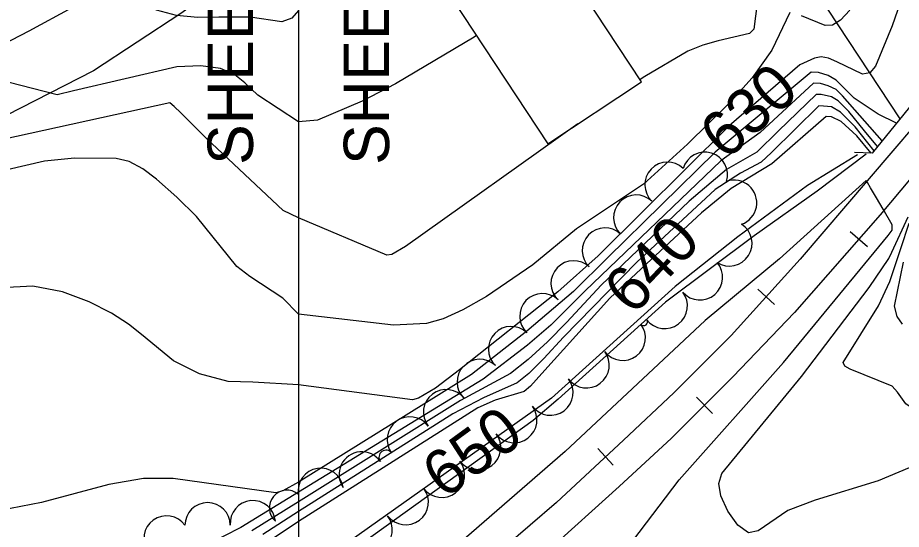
# Model space of a CAD drawing. Extents: x 79600 to 91800, y 75600 to 84400.
# Drawn here: x 84876.3 to 85265.8, y 82239.4 to 82464.8 of the extents above; entities that cross this region are included whole.
import ezdxf

# ---------------------------------------------------------------- set-up
doc = ezdxf.new("R2010")
doc.units = 0
for name, color, linetype in [('084-085$0$GRID', 7, 'Continuous'), ('084-085$0$INDEX', 7, 'Continuous'), ('084-085$0$INTER', 7, 'Continuous'), ('084-085$0$ROAD', 7, 'Continuous'), ('084-085$0$TI_SHEET', 7, 'Continuous'), ('084-085$0$TREES', 7, 'Continuous'), ('084-090$0$BLDG', 7, 'Continuous'), ('084-090$0$BRIDGE', 7, 'Continuous'), ('084-090$0$GRID', 7, 'Continuous'), ('084-090$0$INDEX', 7, 'Continuous'), ('084-090$0$INDXLBL', 7, 'Continuous'), ('084-090$0$INTER', 7, 'Continuous'), ('084-090$0$ROAD', 7, 'Continuous'), ('084-090$0$RR', 7, 'Continuous'), ('084-090$0$TI_SHEET', 7, 'Continuous'), ('084-090$0$TREES', 7, 'Continuous')]:
    doc.layers.add(name, color=color, linetype=linetype)

# ---------------------------------------------------------------- blocks, each defined once
blk = doc.blocks.new('084-090$0$RRTICK100')
blk.add_line((0, -5), (0, 5))

msp = doc.modelspace()

# ---------------------------------------------------------------- linework, layer by layer
at = {"layer": '084-085$0$GRID'}
msp.add_line((85000, 84000), (85000, 80000), dxfattribs=at)
at = {"layer": '084-085$0$INDEX'}
for points in [[(85000, 82303.04), (84979.93, 82304.26), (84969.03, 82304.58), (84956.4, 82307.95), (84944.99, 82313.68), (84930.81, 82325.16), (84925.08, 82329.73), (84917.59, 82334.63), (84907.75, 82339.66), (84895.97, 82343.97), (84882.92, 82346.55), (84843.28, 82344.4), (84808.97, 82345.03), (84798.34, 82343.88), (84787.45, 82341.31)], [(85000, 82242.85), (84981.79, 82230.57)]]:
    msp.add_lwpolyline(points, dxfattribs=at)
at = {"layer": '084-085$0$INTER'}
for points in [[(85000, 82468.03), (84997.16, 82464.63), (84992.74, 82463.02), (84978.7, 82465.06), (84964.89, 82465.11), (84955.7, 82464.96), (84946.24, 82465.81), (84937.48, 82468.22), (84930.08, 82471.41), (84924.64, 82474.25), (84921.56, 82475.99), (84920.44, 82477.28), (84923.96, 82489.01), (84924.41, 82490.84), (84917.34, 82499.54), (84906.76, 82518.7), (84892.54, 82541.22), (84878.81, 82560.85), (84872.17, 82570.21)], [(85000, 82418.99), (84982.18, 82430.67), (84976.43, 82436.1), (84971.99, 82439.7), (84965.66, 82442.51), (84957.03, 82443.63), (84946.44, 82443.11), (84900.89, 82432.62), (84893.67, 82430.83), (84866.72, 82437.76)], [(85000, 82376.71), (84993.36, 82379.83), (84959.35, 82411.78), (84948.22, 82422.85), (84945.33, 82425.71), (84943.35, 82427.35), (84863.6, 82409.82), (84852.82, 82407.06), (84839.68, 82405.95), (84819.07, 82408.01), (84811.74, 82408.37), (84803.14, 82407.64), (84782.74, 82402.54), (84765.75, 82396.19), (84761.62, 82394.72), (84760.1, 82394.54), (84758.88, 82394.6), (84783.68, 82416.29), (84789.97, 82421.91), (84801.36, 82436.99)], [(85000, 82334.2), (84993.22, 82341.21), (84978.62, 82350.73), (84972.86, 82355.26), (84955.1, 82377.29), (84946.41, 82385.79), (84937.52, 82393.7), (84931.52, 82398.2), (84925.37, 82401.5), (84919.66, 82402.75), (84901.37, 82402.91), (84888.09, 82401.62), (84871.65, 82397.76)], [(85000, 82260.1), (84993.19, 82256.36), (84990.13, 82255.53), (84944.8, 82261.74), (84931.69, 82261.79), (84916.48, 82259.17), (84886.85, 82251.18), (84868.55, 82247.65), (84865.13, 82247.06)], [(85000, 82255.78), (84974.68, 82240.16), (84922.2, 82213.43)], [(85000, 82251.47), (84979.49, 82238.65)], [(85000, 82247.16), (84984.3, 82237.15)]]:
    msp.add_lwpolyline(points, dxfattribs=at)
at = {"layer": '084-085$0$ROAD'}
for points in [[(84429.82, 82231.01), (84518.24, 82275.92), (84634.39, 82333.42), (84774.34, 82403.66), (84881.4, 82459.07), (84900.29, 82469.29), (84916.55, 82479.79), (84937.27, 82492.66), (84969.9, 82518.15), (84999.9, 82544.53), (85000, 82544.64)], [(85000, 82507.03), (84975.62, 82486.4), (84948.18, 82466.67), (84909.67, 82441.44), (84871.27, 82421.76), (84821.34, 82396.87), (84727.19, 82347.77), (84586.14, 82278.6), (84439.32, 82205.29)]]:
    msp.add_lwpolyline(points, dxfattribs=at)
at = {"layer": '084-085$0$TREES'}
for centre, radius, start, end in [((84994.97, 82248.85), 7.78, 49.6715, 229.6715), ((84960.01, 82241.17), 10, 0.079, 180.079), ((84979.97, 82242.05), 10, 4.9829, 184.9829), ((84941.88, 82235.33), 10, 35.6147, 215.6147)]:
    msp.add_arc(centre, radius, start, end, dxfattribs=at)
at = {"layer": '084-090$0$BLDG'}
msp.add_lwpolyline([(85091.05, 82518.75), (85074.45, 82543.94), (85041.43, 82522.18), (85057.9, 82497.19), (85053.8, 82494.49), (85109.95, 82409.3), (85151.3, 82436.55), (85095.28, 82521.54)], close=True, dxfattribs=at)
at = {"layer": '084-090$0$BRIDGE'}
msp.add_lwpolyline([(85295.42, 82464.24), (85296.7, 82459), (85252.93, 82405.15), (85245.2, 82405.39)], dxfattribs=at)
at = {"layer": '084-090$0$GRID'}
msp.add_line((85000, 84000), (85000, 80000), dxfattribs=at)
at = {"layer": '084-090$0$INDEX'}
for points in [[(85266.41, 82474.95), (85261.78, 82461.24), (85254.41, 82443.41), (85251.89, 82440.49), (85248.68, 82440), (85237.28, 82445.41), (85233.7, 82446.93), (85230.43, 82447.55), (85227.56, 82447.07), (85221.06, 82444.01), (85189.83, 82417.17), (85132.21, 82359.87), (85114.36, 82344.02), (85071.03, 82309.73), (85060.47, 82301.58), (85052.89, 82297.2), (85050.26, 82296.38), (85000, 82303.04)], [(85252.45, 82405.17), (85246.1, 82412.84), (85239.3, 82419.08), (85235.02, 82421.2), (85232.57, 82421.33), (85208.76, 82400.45), (85190.83, 82389.61), (85177.68, 82378.9), (85153.47, 82356.43), (85137.26, 82341.3), (85107.25, 82308.02), (85102.29, 82302.45), (85099.59, 82300.15), (85086.68, 82296.3), (85079.13, 82292.89), (85000, 82242.85)], [(85246.39, 82404.37), (85224.48, 82390.93), (85193.73, 82368.28), (85166.04, 82346.44), (85111.65, 82297.15), (85000, 82218.08)], [(85338.61, 82255.23), (85337.37, 82256.23), (85333.4, 82258.83), (85328.67, 82259.47), (85308.04, 82269.65), (85278.7, 82287.12), (85267.73, 82294.7), (85264.1, 82299.83), (85261.74, 82302.49), (85243.28, 82309.97), (85240.85, 82311.31), (85240.2, 82312.91), (85255.64, 82337.87), (85260.64, 82348.6), (85264.84, 82360.95), (85265.5, 82363.18), (85269.16, 82374.24)]]:
    msp.add_lwpolyline(points, dxfattribs=at)
at = {"layer": '084-090$0$INTER'}
for points in [[(85278.8, 82583.44), (85260.9, 82565.03), (85247.1, 82553.56), (85242.78, 82550), (85240.21, 82546.93), (85234.45, 82523.49), (85232.69, 82516.57), (85223.98, 82498.18), (85220.75, 82492.17), (85218.66, 82488.96), (85212.17, 82489.31), (85208.71, 82488.99), (85205.58, 82486.14), (85203.43, 82479.96), (85201.43, 82465.47), (85200.78, 82459.73), (85198.83, 82457.92), (85185.02, 82454.57), (85178.34, 82452.67), (85171.61, 82450.07), (85152.67, 82438.96), (85150.65, 82437.53)], [(85216.67, 82467.06), (85208.75, 82450.49), (85200.09, 82438.29), (85190.41, 82427.77), (85171.51, 82409.06), (85152.18, 82391.54), (85122.64, 82371.72), (85103.4, 82355.86), (85082.97, 82341.98), (85072.52, 82336.06), (85063.86, 82332.18), (85056.49, 82330.13), (85041.9, 82329.41), (85000, 82334.2)], [(85243.08, 82468.14), (85239, 82463.69), (85235.45, 82461.56), (85232.22, 82461.39), (85221.78, 82465.7)], [(85078.56, 82456.92), (85077.51, 82456.25), (85042.84, 82435.7), (85028.18, 82428.07), (85008.47, 82419.66), (85000, 82418.99)], [(85263.66, 82418.36), (85255.56, 82422.34), (85244.95, 82429.35), (85237.07, 82437.23), (85233.55, 82439.29), (85229.24, 82440.62), (85226.05, 82440.78), (85183.68, 82405.56), (85136.46, 82359.18), (85121.26, 82344.19), (85100.77, 82326.7), (85076.25, 82307.62), (85000, 82260.1)], [(85257.33, 82410.57), (85239.85, 82430.38), (85236.98, 82433.24), (85233.54, 82434.75), (85230.18, 82435.84), (85227.06, 82435.94), (85203.53, 82414.3), (85186.2, 82401.74), (85126.48, 82344.42), (85111.29, 82329.33), (85101.05, 82320.49), (85081.48, 82305.51), (85000, 82255.78)], [(85255.27, 82408.04), (85249.5, 82414.99), (85242.64, 82423.53), (85237.95, 82428.22), (85235.06, 82429.93), (85230.39, 82430.94), (85228.22, 82430.92), (85211.61, 82415.01), (85202.03, 82405.64), (85188.72, 82397.93), (85172.21, 82383.98), (85133.49, 82346.99), (85118.31, 82330.73), (85109.76, 82321.99), (85101.34, 82314.28), (85093.51, 82308), (85071.46, 82296.21), (85000, 82251.47)], [(85253.8, 82406.23), (85245.43, 82416.69), (85238.92, 82423.21), (85235.04, 82425.51), (85231.47, 82425.88), (85229.46, 82425.98), (85208.53, 82405.47), (85203.99, 82401.13), (85194.88, 82396.25), (85183.66, 82389.15), (85149.21, 82357.11), (85116.84, 82324), (85108.22, 82314.64), (85101.63, 82308.06), (85096.51, 82303.9), (85081.57, 82297.38), (85068.05, 82290.28), (85000, 82247.16)], [(85123.14, 82417.99), (85047.22, 82364.07), (85041.27, 82360.47), (85038.98, 82360.17), (85000, 82376.71)], [(85250.24, 82404.69), (85228.72, 82388.39), (85200.87, 82368.76), (85161.87, 82339.55), (85114.58, 82296.72), (85103.55, 82287.37), (85000, 82212.97)], [(85147.49, 82234.27), (85167.84, 82261.22), (85213.85, 82312.95), (85247.63, 82353.9), (85259.95, 82368.81), (85261.71, 82371.22), (85261.69, 82373.58), (85257.79, 82380.46), (85254.8, 82385.52), (85252.25, 82389.82), (85250.82, 82392.22), (85250.29, 82393.11), (85212.01, 82358.58), (85179.38, 82331.38), (85117.6, 82273.68), (85051.74, 82216.46)], [(85323.86, 82256.54), (85323.1, 82257.26), (85315.47, 82261.78), (85298.34, 82268.5), (85292.66, 82271.62), (85288.4, 82272.73), (85282.88, 82272.27), (85255.53, 82260.76), (85227.74, 82252.24), (85215.82, 82247.67), (85202.65, 82238.73), (85198.4, 82237.85), (85193.73, 82241.27), (85189.29, 82247.43), (85186.22, 82254.1), (85185.4, 82259.54), (85186.65, 82264.05), (85221.71, 82306.79), (85251.63, 82345.88), (85260.29, 82358.71), (85261.55, 82361.46), (85268.84, 82377.12)], [(85266.3, 82329.85), (85263.95, 82333.09), (85262.69, 82337.74), (85266.75, 82357.11)]]:
    msp.add_lwpolyline(points, dxfattribs=at)
at = {"layer": '084-090$0$ROAD'}
msp.add_lwpolyline([(85265.2, 82420.25), (85137.7, 82613.67), (85129.47, 82618.38), (85119.56, 82620.9), (85112.63, 82619.75), (85105.26, 82615.2), (85061.86, 82569.85), (85026.42, 82532.29), (85000.73, 82507.64), (85000, 82507.03)], dxfattribs=at)
at = {"layer": '084-090$0$RR'}
for points in [[(86153.28, 83943.88), (85933.9, 83485.8), (85758.12, 83119.71), (85690.49, 82979.78), (85674.9, 82948.29), (85659.44, 82919.26), (85642.77, 82887.91), (85628.81, 82863.07), (85611.2, 82832.49), (85591.44, 82800.8), (85571.68, 82769.57), (85544.13, 82730.24), (85511.37, 82685.91), (85471.43, 82634.57), (85256.44, 82378.02), (85218.73, 82334.88), (85191.53, 82306.51), (85164.47, 82279.53), (85141.37, 82258.31), (85109.84, 82229.74), (85084.12, 82208.03), (85052.41, 82183.17), (85018.39, 82157.2), (85000, 82144.89)], [(86139.68, 83943.87), (86090.93, 83842.75), (85923.18, 83492.02), (85725.74, 83083.88), (85678.84, 82986.92), (85656.12, 82942.7), (85643.25, 82917.41), (85629, 82890.71), (85615.33, 82867.42), (85596.8, 82836.67), (85573.71, 82798.77), (85557.74, 82774.06), (85536.59, 82743.44), (85505.99, 82699.75), (85477.03, 82661.95), (85312.39, 82465.02), (85221.12, 82358.37), (85190.73, 82324.72), (85165.51, 82299.46), (85143.33, 82278.71), (85113.8, 82251.24), (85078.9, 82221.26)]]:
    msp.add_lwpolyline(points, dxfattribs=at)
at = {"layer": '084-090$0$TREES'}
for centre, radius, start, end in [((85179.2, 82395.57), 10, 343.3041, 163.3041), ((85162.73, 82391.2), 10, 46.399, 226.399), ((85192.07, 82383.25), 10, 289.1755, 109.1755), ((85148.94, 82376.72), 10, 46.399, 226.399), ((85189.97, 82365.38), 10, 237.4378, 57.4378), ((85135.14, 82362.24), 10, 46.399, 226.399), ((85121.35, 82347.75), 10, 46.399, 226.399), ((85177.02, 82350.42), 10, 220.7876, 40.7876), ((85107.56, 82333.27), 10, 46.399, 226.399), ((85161.49, 82337.82), 10, 217.348, 37.348), ((85152.26, 82330.78), 1.61, 217.1281, 37.1281), ((85093.77, 82318.79), 10, 46.399, 226.399), ((85143, 82323.77), 10, 217.1281, 37.1281), ((85127.05, 82311.7), 10, 217.1281, 37.1281), ((85079.97, 82304.3), 10, 46.399, 226.399), ((85111.11, 82299.63), 10, 217.1281, 37.1281), ((85065.14, 82290.98), 10, 37.441, 217.441), ((85095.16, 82287.55), 10, 217.1281, 37.1281), ((85049.16, 82278.95), 10, 36.5564, 216.5564), ((85079.22, 82275.48), 10, 217.1281, 37.1281), ((85027.96, 82263.55), 10, 35.0594, 215.0594), ((85038.64, 82271.14), 3.11, 36.5564, 216.5564), ((85063.27, 82263.41), 10, 217.1281, 37.1281), ((85009.88, 82256.29), 10, 8.699, 188.699), ((85047.32, 82251.34), 10, 217.1281, 37.1281), ((85031.38, 82239.27), 10, 217.1281, 37.1281)]:
    msp.add_arc(centre, radius, start, end, dxfattribs=at)

# ---------------------------------------------------------------- block references
at = {"layer": '084-090$0$RR'}
for p, rotation in [((85247.04, 82367.26), -131.15676236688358), ((85206.17, 82341.82), -132.088466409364), ((85179, 82294.02), -135.08800536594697), ((85135.35, 82271.29), -137.07119198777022)]:
    msp.add_blockref('084-090$0$RRTICK100', p, dxfattribs=dict(at, rotation=rotation))

# ---------------------------------------------------------------- texts
at = {"layer": '084-085$0$TI_SHEET'}
msp.add_text('SHEET', height=20, rotation=90, dxfattribs=at).set_placement((85040, 82400))
at = {"layer": '084-090$0$INDXLBL'}
for s, rotation, p in [('630', 42.0778, (85188.46, 82401.52)), ('640', 46.7243, (85147.57, 82333.15)), ('650', 36.1085, (85064.32, 82252.36))]:
    msp.add_text(s, height=20, rotation=rotation, dxfattribs=at).set_placement(p)
at = {"layer": '084-090$0$TI_SHEET'}
msp.add_text('SHEET', height=20, rotation=90, dxfattribs=at).set_placement((84980, 82400))

doc.saveas('drawing.dxf')
